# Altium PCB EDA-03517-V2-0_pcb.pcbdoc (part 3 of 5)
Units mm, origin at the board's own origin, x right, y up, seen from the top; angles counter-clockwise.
Board outline 220 x 264 mm, 8 copper layers (Top Layer, L2, L3, L4, L5, L6, L7, Bottom Layer), stack 2.18 mm thick; 439 components, 290 nets, 1011 pads, 273 vias.
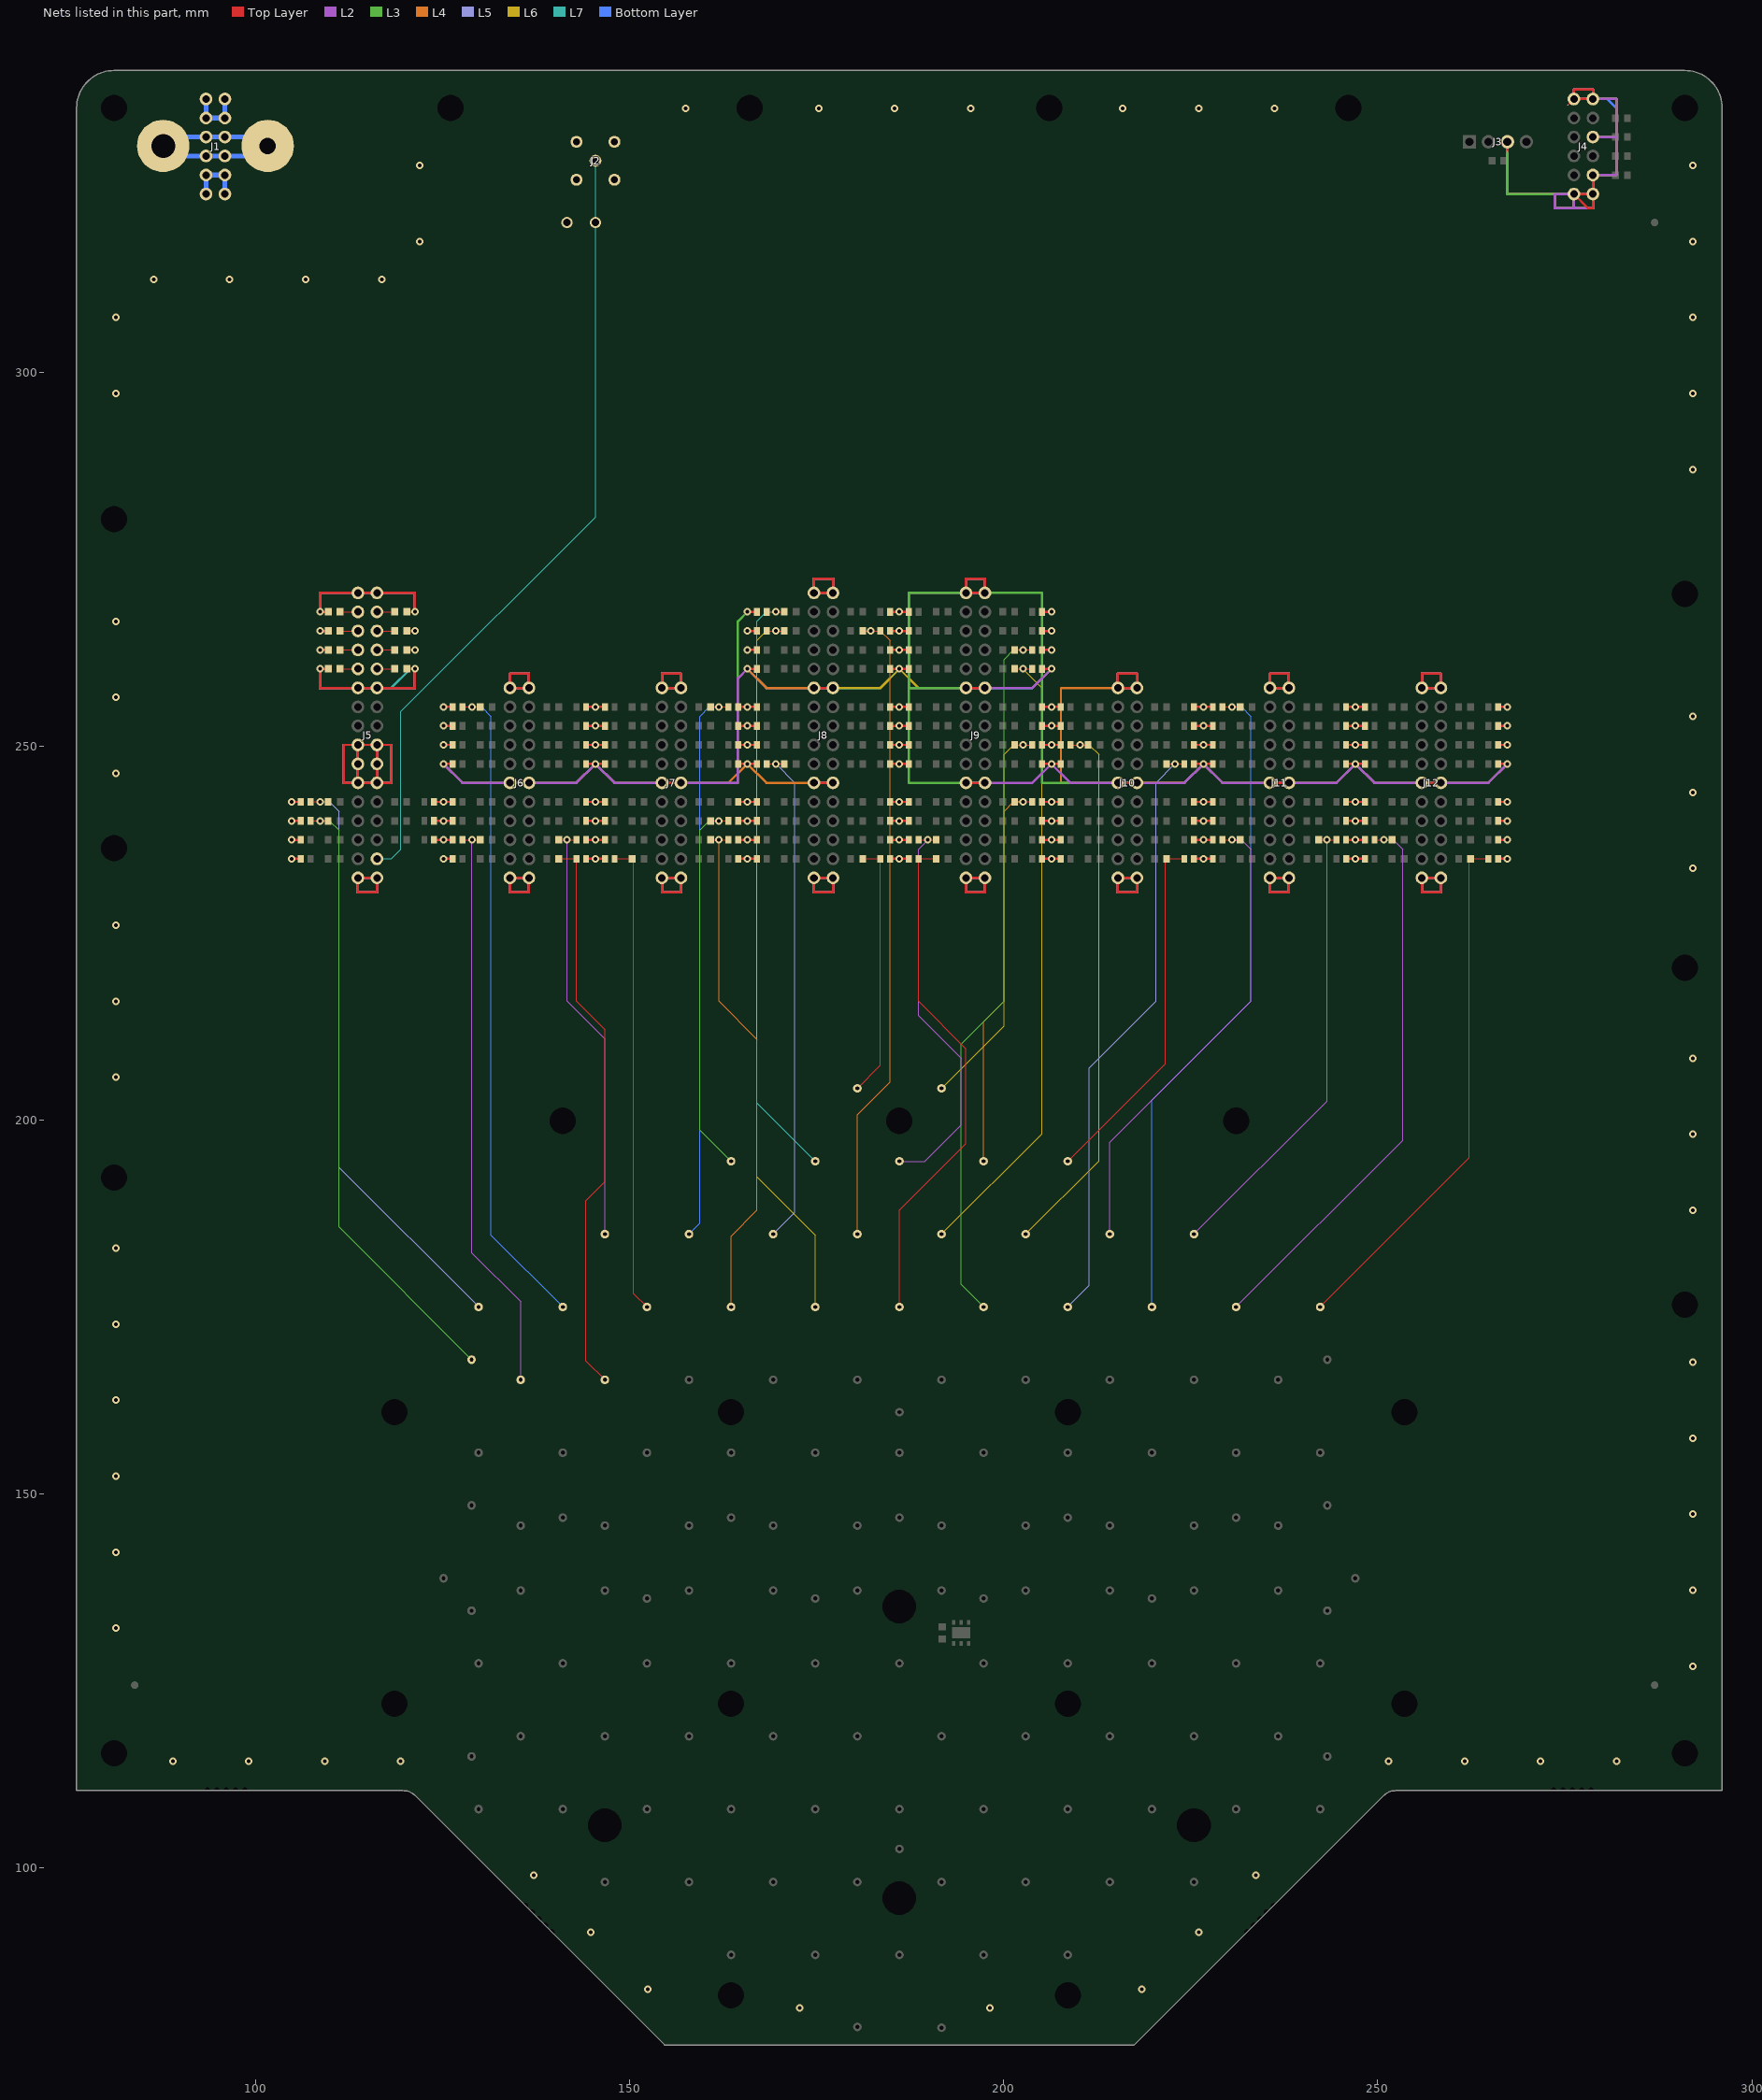
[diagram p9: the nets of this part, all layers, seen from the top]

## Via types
v1: diameter 1, hole 0.5, Top Layer to Bottom Layer, tented both sides, 273 vias

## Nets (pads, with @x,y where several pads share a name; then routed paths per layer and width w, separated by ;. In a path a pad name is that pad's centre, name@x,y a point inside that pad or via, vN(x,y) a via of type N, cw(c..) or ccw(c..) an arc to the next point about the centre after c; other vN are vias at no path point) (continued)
GND: B2.1 C2.2 C3.2 C4.2 C5.2 C6.2 C7.2 C8.2 C9.2 J2.2 J3.3 J4.1 J4.2 J4.3 J4.7 J4.11 J4.12 J5.1 J5.2 J5.11 J5.12 J5.13 J5.14 J5.15 J5.16 J5.21 J5.22 J5.31 J5.32 J6.1 J6.2 J6.11 J6.12 J6.21 J6.22 J7.1 J7.2 J7.11 J7.12 J7.21 J7.22 J8.1 J8.2 J8.11 J8.12 J8.21 J8.22 J8.31 J8.32 J9.1 J9.2 J9.11 J9.12 J9.21 J9.22 J9.31 J9.32 J10.1 J10.2 J10.11 J10.12 J10.21 J10.22 J11.1 J11.2 J11.11 J11.12 J11.21 J11.22 J12.1 J12.2 J12.11 J12.12 J12.21 J12.22 NT1.1 NT2.1 RB1.2 RB2.2 RB3.2 RB4.2 RB5.2 RB6.2 RB7.2 RB8.2 RB9.2 RB10.2 RB11.2 RB12.2 RB13.2 RB14.2 RB15.2 RB16.2 RB17.2 RB18.2 RB19.2 RB20.2 RB21.2 RB22.2 RB23.2 RB24.2 RB25.2 RB26.2 RB27.2 RB28.2 RB29.2 RB30.2 RB31.2 RB32.2 RB33.2 RB34.2 RB35.2 RB36.2 RB37.2 RB38.2 RB39.2 RB40.2 RB41.2 RB42.2 RB43.2 RB44.2 RB45.2 RB46.2 RB47.2 RB48.2 RB49.2 RB50.2 RB51.2 RB52.2 RB53.2 RB54.2 RB55.2 RB56.2 RB57.2 RB58.2 RB59.2 RB60.2 RB61.2 RB62.2 RB63.2 RB64.2 RB65.2 RB66.2 RB67.2 RB68.2 RB69.2 RB70.2 RB71.2 RB72.2 RB73.2 RB74.2 RB75.2 RB76.2 RB77.2 RB78.2 RB79.2 RB80.2 RB81.2 RB82.2 RB83.2 RB84.2 RB85.2 RB86.2 RB87.2 RB88.2 RB89.2 RB90.2 RB91.2 RB92.2 RB93.2 RB94.2 RB95.2 RB96.2 RB97.2 RB98.2 RB99.2 RB100.2 RB101.2 RB102.2 RB103.2 RB104.2 RB105.2 RB106.2 RB107.2 RB108.2 RB109.2 RB110.2 RB111.2 RB112.2 RB113.2 RB114.2 RB115.2 RB116.2 RB117.2 RB118.2 RB119.2 RB120.2 RB121.2 RB122.2 RB123.2 RB124.2 RB125.2 RB126.2 RB127.2 RB128.2 RB129.2 RB130.2 RB131.2 RB132.2 RB133.2 RB134.2 RB135.2 | length 2863.4
  Top Layer w0.152: NT1.1@275.41,335.735 J4.12@276.225,336.55
  Top Layer w0.305: v1(104.775,234.95) RB121.2@106.03,234.95 ; v1(104.775,237.49) RB105.2@106.03,237.49 ; v1(104.775,240.03) RB89.2@106.03,240.03 ; v1(104.775,242.57) RB73.2@106.03,242.57 ; v1(108.585,262.89) C6.2@109.69,262.89 ; v1(108.585,265.43) C4.2@109.69,265.43 ; C8.2@109.69,260.35 v1(108.585,260.35) 108.585,257.81 J5.22@113.665,257.81 J5.21@116.205,257.81 121.285,257.81 v1(121.285,260.35) C9.2@120.18,260.35 ; C2.2@109.69,267.97 v1(108.585,267.97) 108.585,270.51 J5.32@113.665,270.51 J5.31@116.205,270.51 121.285,270.51 v1(121.285,267.97) C3.2@120.18,267.97 ; C7.2@120.18,262.89 v1(121.285,262.89) ; C5.2@120.18,265.43 v1(121.285,265.43) ; RB106.2@123.84,237.49 v1(125.095,237.49) RB112.2@126.35,237.49 ; RB90.2@123.84,240.03 v1(125.095,240.03) RB96.2@126.35,240.03 ; RB74.2@123.84,242.57 v1(125.095,242.57) RB80.2@126.35,242.57 ; v1(125.095,234.95) RB127.2@126.35,234.95 ; v1(125.095,247.65) RB59.2@126.35,247.65 ; v1(125.095,250.19) RB45.2@126.35,250.19 ; v1(125.095,252.73) RB31.2@126.35,252.73 ; v1(125.095,255.27) RB17.2@126.35,255.27 ; J6.12@133.985,245.11 J6.11@136.525,245.11 ; RB122.2@144.16,234.95 v1(145.415,234.95) RB123.2@146.67,234.95 ; RB107.2@144.16,237.49 v1(145.415,237.49) RB108.2@146.67,237.49 ; RB91.2@144.16,240.03 v1(145.415,240.03) RB92.2@146.67,240.03 ; RB75.2@144.16,242.57 v1(145.415,242.57) RB76.2@146.67,242.57 ; RB60.2@144.16,247.65 v1(145.415,247.65) RB61.2@146.67,247.65 ; RB46.2@144.16,250.19 v1(145.415,250.19) RB47.2@146.67,250.19 ; RB32.2@144.16,252.73 v1(145.415,252.73) RB33.2@146.67,252.73 ; RB18.2@144.16,255.27 v1(145.415,255.27) RB19.2@146.67,255.27 ; J7.12@154.305,245.11 J7.11@156.845,245.11 ; RB128.2@164.48,234.95 v1(165.735,234.95) RB124.2@166.99,234.95 ; RB113.2@164.48,237.49 v1(165.735,237.49) RB109.2@166.99,237.49 ; RB97.2@164.48,240.03 v1(165.735,240.03) RB93.2@166.99,240.03 ; RB81.2@164.48,242.57 v1(165.735,242.57) RB77.2@166.99,242.57 ; RB62.2@164.48,247.65 v1(165.735,247.65) RB63.2@166.99,247.65 ; RB48.2@164.48,250.19 v1(165.735,250.19) RB49.2@166.99,250.19 ; RB34.2@164.48,252.73 v1(165.735,252.73) RB35.2@166.99,252.73 ; RB20.2@164.48,255.27 v1(165.735,255.27) RB21.2@166.99,255.27 ; v1(165.735,260.35) RB13.2@166.99,260.35 ; v1(165.735,262.89) RB9.2@166.99,262.89 ; v1(165.735,265.43) RB5.2@166.99,265.43 ; v1(165.735,267.97) RB1.2@166.99,267.97 ; J8.12@174.625,245.11 J8.11@177.165,245.11 ; J8.22@174.625,257.81 J8.21@177.165,257.81 ; RB125.2@184.8,234.95 v1(186.055,234.95) RB129.2@187.31,234.95 ; RB110.2@184.8,237.49 v1(186.055,237.49) RB114.2@187.31,237.49 ; RB94.2@184.8,240.03 v1(186.055,240.03) RB98.2@187.31,240.03 ; RB78.2@184.8,242.57 v1(186.055,242.57) RB82.2@187.31,242.57 ; RB64.2@184.8,247.65 v1(186.055,247.65) RB66.2@187.31,247.65 ; RB50.2@184.8,250.19 v1(186.055,250.19) RB52.2@187.31,250.19 ; RB36.2@184.8,252.73 v1(186.055,252.73) RB38.2@187.31,252.73 ; RB22.2@184.8,255.27 v1(186.055,255.27) RB24.2@187.31,255.27 ; RB14.2@184.8,260.35 v1(186.055,260.35) RB16.2@187.31,260.35 ; RB10.2@184.8,262.89 v1(186.055,262.89) RB12.2@187.31,262.89 ; RB6.2@184.8,265.43 v1(186.055,265.43) RB8.2@187.31,265.43 ; RB2.2@184.8,267.97 v1(186.055,267.97) RB4.2@187.31,267.97 ; J9.12@194.945,245.11 J9.11@197.485,245.11 ; J9.22@194.945,257.81 J9.21@197.485,257.81 ; RB126.2@205.12,234.95 v1(206.375,234.95) RB130.2@207.63,234.95 ; RB111.2@205.12,237.49 v1(206.375,237.49) RB115.2@207.63,237.49 ; RB95.2@205.12,240.03 v1(206.375,240.03) RB99.2@207.63,240.03 ; RB79.2@205.12,242.57 v1(206.375,242.57) RB83.2@207.63,242.57 ; RB65.2@205.12,247.65 v1(206.375,247.65) RB67.2@207.63,247.65 ; RB51.2@205.12,250.19 v1(206.375,250.19) RB53.2@207.63,250.19 ; RB37.2@205.12,252.73 v1(206.375,252.73) RB39.2@207.63,252.73 ; RB23.2@205.12,255.27 v1(206.375,255.27) RB25.2@207.63,255.27 ; RB15.2@205.12,260.35 v1(206.375,260.35) ; RB11.2@205.12,262.89 v1(206.375,262.89) ; RB7.2@205.12,265.43 v1(206.375,265.43) ; RB3.2@205.12,267.97 v1(206.375,267.97) ; J10.12@215.265,245.11 J10.11@217.805,245.11 ; RB131.2@225.44,234.95 v1(226.695,234.95) RB132.2@227.95,234.95 ; RB116.2@225.44,237.49 v1(226.695,237.49) RB117.2@227.95,237.49 ; RB100.2@225.44,240.03 v1(226.695,240.03) RB101.2@227.95,240.03 ; RB84.2@225.44,242.57 v1(226.695,242.57) RB85.2@227.95,242.57 ; RB68.2@225.44,247.65 RB69.2@227.95,247.65 ; RB54.2@225.44,250.19 RB55.2@227.95,250.19 ; RB40.2@225.44,252.73 v1(226.695,252.73) RB41.2@227.95,252.73 ; RB26.2@225.44,255.27 v1(226.695,255.27) RB27.2@227.95,255.27 ; J11.12@235.585,245.11 J11.11@238.125,245.11 ; RB118.2@245.76,237.49 v1(247.015,237.49) RB119.2@248.27,237.49 ; RB102.2@245.76,240.03 v1(247.015,240.03) RB103.2@248.27,240.03 ; RB86.2@245.76,242.57 v1(247.015,242.57) RB87.2@248.27,242.57 ; RB70.2@245.76,247.65 v1(247.015,247.65) RB71.2@248.27,247.65 ; RB56.2@245.76,250.19 v1(247.015,250.19) RB57.2@248.27,250.19 ; RB42.2@245.76,252.73 v1(247.015,252.73) RB43.2@248.27,252.73 ; RB28.2@245.76,255.27 v1(247.015,255.27) RB29.2@248.27,255.27 ; RB133.2@245.775,234.95 v1(247.015,234.95) RB134.2@248.27,234.95 ; J12.12@255.905,245.11 J12.11@258.445,245.11 ; RB135.2@266.08,234.95 v1(267.335,234.95) ; RB120.2@266.08,237.49 v1(267.335,237.49) ; RB104.2@266.08,240.03 v1(267.335,240.03) ; RB88.2@266.08,242.57 v1(267.335,242.57) ; RB72.2@266.08,247.65 v1(267.335,247.65) ; RB58.2@266.08,250.19 v1(267.335,250.19) ; RB44.2@266.08,252.73 v1(267.335,252.73) ; RB30.2@266.08,255.27 v1(267.335,255.27) ; NT2.1@267.335,329.565 J3.3@267.335,330.835 ; J4.3@278.765,326.39 J4.1@278.765,323.85 ; J5.12@113.665,245.11 J5.14@113.665,247.65 J5.16@113.665,250.19 ; J5.12@113.665,245.11 111.76,245.11 111.76,250.19 J5.16@113.665,250.19 ; J5.12@113.665,245.11 J5.11@116.205,245.11 ; J5.16@113.665,250.19 J5.15@116.205,250.19 ; J5.11@116.205,245.11 J5.13@116.205,247.65 J5.15@116.205,250.19 ; J5.11@116.205,245.11 118.11,245.11 118.11,250.19 J5.15@116.205,250.19 ; J4.1@278.765,323.85 278.765,321.945 278.13,321.945 J4.2@276.225,323.85 J4.1@278.765,323.85 ; 113.665,230.505 116.205,230.505 J5.1@116.205,232.41 J5.2@113.665,232.41 113.665,230.505 ; 133.985,230.505 136.525,230.505 J6.1@136.525,232.41 J6.2@133.985,232.41 133.985,230.505 ; J6.22@133.985,257.81 133.985,259.715 136.525,259.715 J6.21@136.525,257.81 J6.22@133.985,257.81 ; 154.305,230.505 156.845,230.505 J7.1@156.845,232.41 J7.2@154.305,232.41 154.305,230.505 ; J7.22@154.305,257.81 154.305,259.715 156.845,259.715 J7.21@156.845,257.81 J7.22@154.305,257.81 ; 174.625,230.505 177.165,230.505 J8.1@177.165,232.41 J8.2@174.625,232.41 174.625,230.505 ; J8.32@174.625,270.51 174.625,272.415 177.165,272.415 J8.31@177.165,270.51 J8.32@174.625,270.51 ; 194.945,230.505 197.485,230.505 J9.1@197.485,232.41 J9.2@194.945,232.41 194.945,230.505 ; J9.32@194.945,270.51 194.945,272.415 197.485,272.415 J9.31@197.485,270.51 J9.32@194.945,270.51 ; 215.265,230.505 217.805,230.505 J10.1@217.805,232.41 J10.2@215.265,232.41 215.265,230.505 ; J10.22@215.265,257.81 215.265,259.715 217.805,259.715 J10.21@217.805,257.81 J10.22@215.265,257.81 ; 235.585,230.505 238.125,230.505 J11.1@238.125,232.41 J11.2@235.585,232.41 235.585,230.505 ; J11.22@235.585,257.81 235.585,259.715 238.125,259.715 J11.21@238.125,257.81 J11.22@235.585,257.81 ; 255.905,230.505 258.445,230.505 J12.1@258.445,232.41 J12.2@255.905,232.41 255.905,230.505 ; J12.22@255.905,257.81 255.905,259.715 258.445,259.715 J12.21@258.445,257.81 J12.22@255.905,257.81 ; J4.12@276.225,336.55 276.225,337.82 278.765,337.82 J4.11@278.765,336.55 J4.12@276.225,336.55
  L2 w0.305: v1(108.585,260.35) 108.585,257.81 J5.22@113.665,257.81 J5.21@116.205,257.81 121.285,257.81 v1(121.285,260.35) ; v1(108.585,267.97) 108.585,270.51 J5.32@113.665,270.51 J5.31@116.205,270.51 121.285,270.51 v1(121.285,267.97) ; v1(125.095,247.65) 127.635,245.11 142.875,245.11 v1(145.415,247.65) 147.955,245.11 J7.12@154.305,245.11 J7.11@156.845,245.11 164.465,245.11 164.465,259.08 v1(165.735,260.35) ; J8.12@174.625,245.11 J8.11@177.165,245.11 ; J8.22@174.625,257.81 J8.21@177.165,257.81 ; J9.12@194.945,245.11 203.835,245.11 v1(206.375,247.65) 208.915,245.11 224.155,245.11 v1(226.695,247.65) 229.235,245.11 J11.12@235.585,245.11 J11.11@238.125,245.11 244.475,245.11 v1(247.015,247.65) 249.555,245.11 J12.12@255.905,245.11 J12.11@258.445,245.11 264.795,245.11 v1(267.335,247.65) ; J9.22@194.945,257.81 203.835,257.81 v1(206.375,260.35) ; J4.7@278.765,331.47 281.94,331.47 ; J5.12@113.665,245.11 111.76,245.11 111.76,250.19 J5.16@113.665,250.19 ; J5.12@113.665,245.11 J5.14@113.665,247.65 J5.16@113.665,250.19 ; J5.12@113.665,245.11 J5.11@116.205,245.11 ; J5.16@113.665,250.19 J5.15@116.205,250.19 ; J5.11@116.205,245.11 118.11,245.11 118.11,250.19 J5.15@116.205,250.19 ; J5.11@116.205,245.11 J5.13@116.205,247.65 J5.15@116.205,250.19 ; 276.225,321.945 273.685,321.945 273.685,323.85 J4.2@276.225,323.85 ; 276.225,321.945 278.765,321.945 J4.1@278.765,323.85 ; 276.225,321.945 J4.2@276.225,323.85 ; J4.2@276.225,323.85 J4.1@278.765,323.85 ; J4.1@278.765,323.85 J4.3@278.765,326.39 281.94,326.39 281.94,331.47 ; J4.11@278.765,336.55 281.94,336.55 281.94,331.47 ; J4.11@278.765,336.55 278.765,337.82 276.225,337.82 J4.12@276.225,336.55 J4.11@278.765,336.55 ; 113.665,230.505 116.205,230.505 J5.1@116.205,232.41 J5.2@113.665,232.41 113.665,230.505 ; 133.985,230.505 136.525,230.505 J6.1@136.525,232.41 J6.2@133.985,232.41 133.985,230.505 ; J6.22@133.985,257.81 133.985,259.715 136.525,259.715 J6.21@136.525,257.81 J6.22@133.985,257.81 ; 154.305,230.505 156.845,230.505 J7.1@156.845,232.41 J7.2@154.305,232.41 154.305,230.505 ; J7.22@154.305,257.81 154.305,259.715 156.845,259.715 J7.21@156.845,257.81 J7.22@154.305,257.81 ; 174.625,230.505 177.165,230.505 J8.1@177.165,232.41 J8.2@174.625,232.41 174.625,230.505 ; J8.32@174.625,270.51 174.625,272.415 177.165,272.415 J8.31@177.165,270.51 J8.32@174.625,270.51 ; 194.945,230.505 197.485,230.505 J9.1@197.485,232.41 J9.2@194.945,232.41 194.945,230.505 ; J9.32@194.945,270.51 194.945,272.415 197.485,272.415 J9.31@197.485,270.51 J9.32@194.945,270.51 ; 215.265,230.505 217.805,230.505 J10.1@217.805,232.41 J10.2@215.265,232.41 215.265,230.505 ; J10.22@215.265,257.81 215.265,259.715 217.805,259.715 J10.21@217.805,257.81 J10.22@215.265,257.81 ; 235.585,230.505 238.125,230.505 J11.1@238.125,232.41 J11.2@235.585,232.41 235.585,230.505 ; J11.22@235.585,257.81 235.585,259.715 238.125,259.715 J11.21@238.125,257.81 J11.22@235.585,257.81 ; 255.905,230.505 258.445,230.505 J12.1@258.445,232.41 J12.2@255.905,232.41 255.905,230.505 ; J12.22@255.905,257.81 255.905,259.715 258.445,259.715 J12.21@258.445,257.81 J12.22@255.905,257.81
  L3 w0.305: v1(108.585,260.35) 108.585,257.81 J5.22@113.665,257.81 J5.21@116.205,257.81 121.285,257.81 v1(121.285,260.35) ; v1(108.585,267.97) 108.585,270.51 J5.32@113.665,270.51 J5.31@116.205,270.51 121.285,270.51 v1(121.285,267.97) ; v1(125.095,247.65) 127.635,245.11 142.875,245.11 v1(145.415,247.65) 147.955,245.11 J7.12@154.305,245.11 J7.11@156.845,245.11 164.465,245.11 164.465,266.7 v1(165.735,267.97) ; J8.12@174.625,245.11 J8.11@177.165,245.11 ; J8.22@174.625,257.81 J8.21@177.165,257.81 ; J9.11@197.485,245.11 187.325,245.11 187.325,257.81 ; J9.21@197.485,257.81 J9.22@194.945,257.81 187.325,257.81 ; J10.11@217.805,245.11 J10.12@215.265,245.11 205.105,245.11 205.105,270.51 J9.31@197.485,270.51 ; v1(226.695,247.65) 229.235,245.11 J11.12@235.585,245.11 J11.11@238.125,245.11 244.475,245.11 v1(247.015,247.65) 249.555,245.11 J12.12@255.905,245.11 J12.11@258.445,245.11 264.795,245.11 v1(267.335,247.65) ; J3.3@267.335,330.835 267.335,323.85 273.685,323.85 ; J4.7@278.765,331.47 281.94,331.47 ; J5.12@113.665,245.11 J5.11@116.205,245.11 ; J5.12@113.665,245.11 J5.14@113.665,247.65 J5.16@113.665,250.19 ; J5.12@113.665,245.11 111.76,245.11 111.76,250.19 J5.16@113.665,250.19 ; J5.16@113.665,250.19 J5.15@116.205,250.19 ; J5.11@116.205,245.11 118.11,245.11 118.11,250.19 J5.15@116.205,250.19 ; J5.11@116.205,245.11 J5.13@116.205,247.65 J5.15@116.205,250.19 ; 187.325,257.81 187.325,270.51 J9.32@194.945,270.51 ; J9.32@194.945,270.51 J9.31@197.485,270.51 ; J9.32@194.945,270.51 194.945,272.415 197.485,272.415 J9.31@197.485,270.51 ; 273.685,323.85 J4.2@276.225,323.85 ; 273.685,323.85 273.685,321.945 276.225,321.945 ; 276.225,321.945 J4.2@276.225,323.85 ; 276.225,321.945 278.765,321.945 J4.1@278.765,323.85 ; J4.2@276.225,323.85 J4.1@278.765,323.85 ; J4.1@278.765,323.85 J4.3@278.765,326.39 281.94,326.39 281.94,331.47 ; J4.11@278.765,336.55 278.765,337.82 276.225,337.82 J4.12@276.225,336.55 J4.11@278.765,336.55 ; J4.11@278.765,336.55 281.94,336.55 281.94,331.47 ; 113.665,230.505 116.205,230.505 J5.1@116.205,232.41 J5.2@113.665,232.41 113.665,230.505 ; 133.985,230.505 136.525,230.505 J6.1@136.525,232.41 J6.2@133.985,232.41 133.985,230.505 ; J6.22@133.985,257.81 J6.21@136.525,257.81 136.525,259.715 133.985,259.715 J6.22@133.985,257.81 ; 154.305,230.505 156.845,230.505 J7.1@156.845,232.41 J7.2@154.305,232.41 154.305,230.505 ; J7.22@154.305,257.81 J7.21@156.845,257.81 156.845,259.715 154.305,259.715 J7.22@154.305,257.81 ; 174.625,230.505 177.165,230.505 J8.1@177.165,232.41 J8.2@174.625,232.41 174.625,230.505 ; J8.32@174.625,270.51 J8.31@177.165,270.51 177.165,272.415 174.625,272.415 J8.32@174.625,270.51 ; 194.945,230.505 197.485,230.505 J9.1@197.485,232.41 J9.2@194.945,232.41 194.945,230.505 ; 215.265,230.505 217.805,230.505 J10.1@217.805,232.41 J10.2@215.265,232.41 215.265,230.505 ; J10.22@215.265,257.81 J10.21@217.805,257.81 217.805,259.715 215.265,259.715 J10.22@215.265,257.81 ; 235.585,230.505 238.125,230.505 J11.1@238.125,232.41 J11.2@235.585,232.41 235.585,230.505 ; J11.22@235.585,257.81 J11.21@238.125,257.81 238.125,259.715 235.585,259.715 J11.22@235.585,257.81 ; 255.905,230.505 258.445,230.505 J12.1@258.445,232.41 J12.2@255.905,232.41 255.905,230.505 ; J12.22@255.905,257.81 J12.21@258.445,257.81 258.445,259.715 255.905,259.715 J12.22@255.905,257.81
  L4 w0.305: v1(108.585,260.35) 108.585,257.81 J5.22@113.665,257.81 J5.21@116.205,257.81 121.285,257.81 v1(121.285,260.35) ; v1(108.585,267.97) 108.585,270.51 J5.32@113.665,270.51 J5.31@116.205,270.51 121.285,270.51 v1(121.285,267.97) ; v1(125.095,247.65) 127.635,245.11 J6.12@133.985,245.11 J6.11@136.525,245.11 142.875,245.11 v1(145.415,247.65) 147.955,245.11 J7.12@154.305,245.11 J7.11@156.845,245.11 163.195,245.11 v1(165.735,247.65) 168.275,245.11 J8.12@174.625,245.11 J8.11@177.165,245.11 ; v1(165.735,260.35) 168.275,257.81 J8.22@174.625,257.81 J8.21@177.165,257.81 ; J9.22@194.945,257.81 J9.21@197.485,257.81 ; v1(267.335,247.65) 264.795,245.11 J12.11@258.445,245.11 J12.12@255.905,245.11 249.555,245.11 v1(247.015,247.65) 244.475,245.11 J11.11@238.125,245.11 J11.12@235.585,245.11 229.235,245.11 v1(226.695,247.65) 224.155,245.11 J10.11@217.805,245.11 J10.12@215.265,245.11 207.645,245.11 207.645,257.81 J10.22@215.265,257.81 ; J3.3@267.335,330.835 267.335,323.85 273.685,323.85 ; J4.7@278.765,331.47 281.94,331.47 ; J5.12@113.665,245.11 111.76,245.11 111.76,250.19 J5.16@113.665,250.19 ; J5.12@113.665,245.11 J5.11@116.205,245.11 ; J5.12@113.665,245.11 J5.14@113.665,247.65 J5.16@113.665,250.19 ; J5.16@113.665,250.19 J5.15@116.205,250.19 ; J5.11@116.205,245.11 118.11,245.11 118.11,250.19 J5.15@116.205,250.19 ; J5.11@116.205,245.11 J5.13@116.205,247.65 J5.15@116.205,250.19 ; J10.22@215.265,257.81 J10.21@217.805,257.81 217.805,259.715 215.265,259.715 J10.22@215.265,257.81 ; 273.685,323.85 J4.2@276.225,323.85 ; 273.685,323.85 273.685,321.945 276.225,321.945 ; 276.225,321.945 J4.2@276.225,323.85 ; 276.225,321.945 278.765,321.945 J4.1@278.765,323.85 ; J4.2@276.225,323.85 J4.1@278.765,323.85 ; J4.1@278.765,323.85 J4.3@278.765,326.39 281.94,326.39 281.94,331.47 ; J4.11@278.765,336.55 281.94,336.55 281.94,331.47 ; J4.11@278.765,336.55 278.765,337.82 276.225,337.82 J4.12@276.225,336.55 J4.11@278.765,336.55 ; 113.665,230.505 116.205,230.505 J5.1@116.205,232.41 J5.2@113.665,232.41 113.665,230.505 ; 133.985,230.505 136.525,230.505 J6.1@136.525,232.41 J6.2@133.985,232.41 133.985,230.505 ; J6.22@133.985,257.81 J6.21@136.525,257.81 136.525,259.715 133.985,259.715 J6.22@133.985,257.81 ; 154.305,230.505 156.845,230.505 J7.1@156.845,232.41 J7.2@154.305,232.41 154.305,230.505 ; J7.22@154.305,257.81 J7.21@156.845,257.81 156.845,259.715 154.305,259.715 J7.22@154.305,257.81 ; 174.625,230.505 177.165,230.505 J8.1@177.165,232.41 J8.2@174.625,232.41 174.625,230.505 ; J8.32@174.625,270.51 J8.31@177.165,270.51 177.165,272.415 174.625,272.415 J8.32@174.625,270.51 ; 194.945,230.505 197.485,230.505 J9.1@197.485,232.41 J9.2@194.945,232.41 194.945,230.505 ; J9.32@194.945,270.51 J9.31@197.485,270.51 197.485,272.415 194.945,272.415 J9.32@194.945,270.51 ; 215.265,230.505 217.805,230.505 J10.1@217.805,232.41 J10.2@215.265,232.41 215.265,230.505 ; 235.585,230.505 238.125,230.505 J11.1@238.125,232.41 J11.2@235.585,232.41 235.585,230.505 ; J11.22@235.585,257.81 J11.21@238.125,257.81 238.125,259.715 235.585,259.715 J11.22@235.585,257.81 ; 255.905,230.505 258.445,230.505 J12.1@258.445,232.41 J12.2@255.905,232.41 255.905,230.505 ; J12.22@255.905,257.81 J12.21@258.445,257.81 258.445,259.715 255.905,259.715 J12.22@255.905,257.81
  L5 w0.305: v1(108.585,260.35) 108.585,257.81 J5.22@113.665,257.81 J5.21@116.205,257.81 121.285,257.81 v1(121.285,260.35) ; v1(108.585,267.97) 108.585,270.51 J5.32@113.665,270.51 J5.31@116.205,270.51 121.285,270.51 v1(121.285,267.97) ; J6.12@133.985,245.11 J6.11@136.525,245.11 ; J7.12@154.305,245.11 J7.11@156.845,245.11 ; v1(165.735,260.35) 168.275,257.81 J8.22@174.625,257.81 J8.21@177.165,257.81 ; J8.12@174.625,245.11 J8.11@177.165,245.11 ; J9.21@197.485,257.81 J9.22@194.945,257.81 187.325,257.81 187.325,270.51 J9.32@194.945,270.51 ; J10.12@215.265,245.11 J10.11@217.805,245.11 ; J11.12@235.585,245.11 J11.11@238.125,245.11 ; J12.12@255.905,245.11 J12.11@258.445,245.11 ; J3.3@267.335,330.835 267.335,323.85 273.685,323.85 ; J4.7@278.765,331.47 281.94,331.47 ; J5.12@113.665,245.11 J5.14@113.665,247.65 J5.16@113.665,250.19 ; J5.12@113.665,245.11 111.76,245.11 111.76,250.19 J5.16@113.665,250.19 ; J5.12@113.665,245.11 J5.11@116.205,245.11 ; J5.16@113.665,250.19 J5.15@116.205,250.19 ; J5.11@116.205,245.11 J5.13@116.205,247.65 J5.15@116.205,250.19 ; J5.11@116.205,245.11 118.11,245.11 118.11,250.19 J5.15@116.205,250.19 ; J9.32@194.945,270.51 194.945,272.415 197.485,272.415 J9.31@197.485,270.51 J9.32@194.945,270.51 ; 273.685,323.85 J4.2@276.225,323.85 ; 273.685,323.85 273.685,321.945 276.225,321.945 ; 276.225,321.945 J4.2@276.225,323.85 ; 276.225,321.945 278.765,321.945 J4.1@278.765,323.85 ; J4.2@276.225,323.85 J4.1@278.765,323.85 ; J4.1@278.765,323.85 J4.3@278.765,326.39 281.94,326.39 281.94,331.47 ; J4.11@278.765,336.55 278.765,337.82 276.225,337.82 J4.12@276.225,336.55 J4.11@278.765,336.55 ; J4.11@278.765,336.55 281.94,336.55 281.94,331.47 ; 113.665,230.505 J5.2@113.665,232.41 J5.1@116.205,232.41 116.205,230.505 113.665,230.505 ; 133.985,230.505 J6.2@133.985,232.41 J6.1@136.525,232.41 136.525,230.505 133.985,230.505 ; J6.22@133.985,257.81 133.985,259.715 136.525,259.715 J6.21@136.525,257.81 J6.22@133.985,257.81 ; 154.305,230.505 J7.2@154.305,232.41 J7.1@156.845,232.41 156.845,230.505 154.305,230.505 ; J7.22@154.305,257.81 154.305,259.715 156.845,259.715 J7.21@156.845,257.81 J7.22@154.305,257.81 ; 174.625,230.505 J8.2@174.625,232.41 J8.1@177.165,232.41 177.165,230.505 174.625,230.505 ; J8.32@174.625,270.51 174.625,272.415 177.165,272.415 J8.31@177.165,270.51 J8.32@174.625,270.51 ; 194.945,230.505 J9.2@194.945,232.41 J9.1@197.485,232.41 197.485,230.505 194.945,230.505 ; 215.265,230.505 J10.2@215.265,232.41 J10.1@217.805,232.41 217.805,230.505 215.265,230.505 ; J10.22@215.265,257.81 215.265,259.715 217.805,259.715 J10.21@217.805,257.81 J10.22@215.265,257.81 ; 235.585,230.505 J11.2@235.585,232.41 J11.1@238.125,232.41 238.125,230.505 235.585,230.505 ; J11.22@235.585,257.81 235.585,259.715 238.125,259.715 J11.21@238.125,257.81 J11.22@235.585,257.81 ; 255.905,230.505 J12.2@255.905,232.41 J12.1@258.445,232.41 258.445,230.505 255.905,230.505 ; J12.22@255.905,257.81 255.905,259.715 258.445,259.715 J12.21@258.445,257.81 J12.22@255.905,257.81
  L6 w0.305: v1(108.585,260.35) 108.585,257.81 J5.22@113.665,257.81 J5.21@116.205,257.81 121.285,257.81 v1(121.285,260.35) ; v1(108.585,267.97) 108.585,270.51 J5.32@113.665,270.51 J5.31@116.205,270.51 121.285,270.51 v1(121.285,267.97) ; J6.12@133.985,245.11 J6.11@136.525,245.11 ; J7.12@154.305,245.11 J7.11@156.845,245.11 ; J8.12@174.625,245.11 J8.11@177.165,245.11 ; J8.22@174.625,257.81 J8.21@177.165,257.81 183.515,257.81 v1(186.055,260.35) 188.595,257.81 J9.22@194.945,257.81 J9.21@197.485,257.81 ; J10.12@215.265,245.11 J10.11@217.805,245.11 ; J11.12@235.585,245.11 J11.11@238.125,245.11 ; J12.12@255.905,245.11 J12.11@258.445,245.11 ; J3.3@267.335,330.835 267.335,323.85 273.685,323.85 ; J4.7@278.765,331.47 281.94,331.47 ; J5.12@113.665,245.11 J5.14@113.665,247.65 J5.16@113.665,250.19 ; J5.12@113.665,245.11 111.76,245.11 111.76,250.19 J5.16@113.665,250.19 ; J5.12@113.665,245.11 J5.11@116.205,245.11 ; J5.16@113.665,250.19 J5.15@116.205,250.19 ; J5.11@116.205,245.11 J5.13@116.205,247.65 J5.15@116.205,250.19 ; J5.11@116.205,245.11 118.11,245.11 118.11,250.19 J5.15@116.205,250.19 ; 273.685,323.85 J4.2@276.225,323.85 ; 273.685,323.85 273.685,321.945 276.225,321.945 ; 276.225,321.945 J4.2@276.225,323.85 ; 276.225,321.945 278.765,321.945 J4.1@278.765,323.85 ; J4.2@276.225,323.85 J4.1@278.765,323.85 ; J4.1@278.765,323.85 J4.3@278.765,326.39 281.94,326.39 281.94,331.47 ; J4.11@278.765,336.55 278.765,337.82 276.225,337.82 J4.12@276.225,336.55 J4.11@278.765,336.55 ; J4.11@278.765,336.55 281.94,336.55 281.94,331.47 ; 113.665,230.505 J5.2@113.665,232.41 J5.1@116.205,232.41 116.205,230.505 113.665,230.505 ; 133.985,230.505 J6.2@133.985,232.41 J6.1@136.525,232.41 136.525,230.505 133.985,230.505 ; J6.22@133.985,257.81 133.985,259.715 136.525,259.715 J6.21@136.525,257.81 J6.22@133.985,257.81 ; 154.305,230.505 J7.2@154.305,232.41 J7.1@156.845,232.41 156.845,230.505 154.305,230.505 ; J7.22@154.305,257.81 154.305,259.715 156.845,259.715 J7.21@156.845,257.81 J7.22@154.305,257.81 ; 174.625,230.505 J8.2@174.625,232.41 J8.1@177.165,232.41 177.165,230.505 174.625,230.505 ; J8.32@174.625,270.51 174.625,272.415 177.165,272.415 J8.31@177.165,270.51 J8.32@174.625,270.51 ; 194.945,230.505 J9.2@194.945,232.41 J9.1@197.485,232.41 197.485,230.505 194.945,230.505 ; J9.32@194.945,270.51 194.945,272.415 197.485,272.415 J9.31@197.485,270.51 J9.32@194.945,270.51 ; 215.265,230.505 J10.2@215.265,232.41 J10.1@217.805,232.41 217.805,230.505 215.265,230.505 ; J10.22@215.265,257.81 215.265,259.715 217.805,259.715 J10.21@217.805,257.81 J10.22@215.265,257.81 ; 235.585,230.505 J11.2@235.585,232.41 J11.1@238.125,232.41 238.125,230.505 235.585,230.505 ; J11.22@235.585,257.81 235.585,259.715 238.125,259.715 J11.21@238.125,257.81 J11.22@235.585,257.81 ; 255.905,230.505 J12.2@255.905,232.41 J12.1@258.445,232.41 258.445,230.505 255.905,230.505 ; J12.22@255.905,257.81 255.905,259.715 258.445,259.715 J12.21@258.445,257.81 J12.22@255.905,257.81
  L7 w0.305: v1(108.585,260.35) 108.585,257.81 J5.22@113.665,257.81 J5.21@116.205,257.81 118.11,257.81 120.65,260.35 v1(121.285,260.35) ; v1(108.585,267.97) 108.585,270.51 J5.32@113.665,270.51 J5.31@116.205,270.51 121.285,270.51 v1(121.285,267.97) ; J6.12@133.985,245.11 J6.11@136.525,245.11 ; J7.12@154.305,245.11 J7.11@156.845,245.11 ; J8.12@174.625,245.11 J8.11@177.165,245.11 ; J8.22@174.625,257.81 J8.21@177.165,257.81 183.515,257.81 v1(186.055,260.35) ; J9.22@194.945,257.81 J9.21@197.485,257.81 203.835,257.81 v1(206.375,260.35) ; J10.12@215.265,245.11 J10.11@217.805,245.11 ; J11.12@235.585,245.11 J11.11@238.125,245.11 ; J12.12@255.905,245.11 J12.11@258.445,245.11 ; J3.3@267.335,330.835 267.335,323.85 273.685,323.85 ; J4.7@278.765,331.47 281.94,331.47 ; J5.12@113.665,245.11 J5.14@113.665,247.65 J5.16@113.665,250.19 ; J5.12@113.665,245.11 111.76,245.11 111.76,250.19 J5.16@113.665,250.19 ; J5.12@113.665,245.11 J5.11@116.205,245.11 J5.13@116.205,247.65 J5.15@116.205,250.19 J5.16@113.665,250.19 ; 273.685,323.85 J4.2@276.225,323.85 ; 273.685,323.85 273.685,321.945 276.225,321.945 ; 276.225,321.945 J4.2@276.225,323.85 ; 276.225,321.945 278.765,321.945 J4.1@278.765,323.85 ; J4.2@276.225,323.85 J4.1@278.765,323.85 ; J4.1@278.765,323.85 J4.3@278.765,326.39 281.94,326.39 281.94,331.47 ; J4.11@278.765,336.55 281.94,336.55 281.94,331.47 ; J4.11@278.765,336.55 278.765,337.82 276.225,337.82 J4.12@276.225,336.55 J4.11@278.765,336.55 ; 113.665,230.505 J5.2@113.665,232.41 J5.1@116.205,232.41 116.205,230.505 113.665,230.505 ; 133.985,230.505 J6.2@133.985,232.41 J6.1@136.525,232.41 136.525,230.505 133.985,230.505 ; J6.22@133.985,257.81 133.985,259.715 136.525,259.715 J6.21@136.525,257.81 J6.22@133.985,257.81 ; 154.305,230.505 J7.2@154.305,232.41 J7.1@156.845,232.41 156.845,230.505 154.305,230.505 ; J7.22@154.305,257.81 154.305,259.715 156.845,259.715 J7.21@156.845,257.81 J7.22@154.305,257.81 ; 174.625,230.505 J8.2@174.625,232.41 J8.1@177.165,232.41 177.165,230.505 174.625,230.505 ; J8.32@174.625,270.51 174.625,272.415 177.165,272.415 J8.31@177.165,270.51 J8.32@174.625,270.51 ; 194.945,230.505 J9.2@194.945,232.41 J9.1@197.485,232.41 197.485,230.505 194.945,230.505 ; J9.32@194.945,270.51 194.945,272.415 197.485,272.415 J9.31@197.485,270.51 J9.32@194.945,270.51 ; 215.265,230.505 J10.2@215.265,232.41 J10.1@217.805,232.41 217.805,230.505 215.265,230.505 ; J10.22@215.265,257.81 215.265,259.715 217.805,259.715 J10.21@217.805,257.81 J10.22@215.265,257.81 ; 235.585,230.505 J11.2@235.585,232.41 J11.1@238.125,232.41 238.125,230.505 235.585,230.505 ; J11.22@235.585,257.81 235.585,259.715 238.125,259.715 J11.21@238.125,257.81 J11.22@235.585,257.81 ; 255.905,230.505 J12.2@255.905,232.41 J12.1@258.445,232.41 258.445,230.505 255.905,230.505 ; J12.22@255.905,257.81 255.905,259.715 258.445,259.715 J12.21@258.445,257.81 J12.22@255.905,257.81
  Bottom Layer w0.305: v1(108.585,260.35) 108.585,257.81 J5.22@113.665,257.81 J5.21@116.205,257.81 121.285,257.81 v1(121.285,260.35) ; v1(108.585,267.97) 108.585,270.51 J5.32@113.665,270.51 J5.31@116.205,270.51 121.285,270.51 v1(121.285,267.97) ; J6.2@133.985,232.41 J6.1@136.525,232.41 ; J6.12@133.985,245.11 J6.11@136.525,245.11 ; J7.2@154.305,232.41 J7.1@156.845,232.41 ; J7.12@154.305,245.11 J7.11@156.845,245.11 ; J8.2@174.625,232.41 J8.1@177.165,232.41 ; J8.12@174.625,245.11 J8.11@177.165,245.11 ; J8.22@174.625,257.81 J8.21@177.165,257.81 ; J9.2@194.945,232.41 J9.1@197.485,232.41 ; J9.22@194.945,257.81 J9.21@197.485,257.81 ; J10.2@215.265,232.41 J10.1@217.805,232.41 ; J10.12@215.265,245.11 J10.11@217.805,245.11 ; J11.2@235.585,232.41 J11.1@238.125,232.41 ; J11.12@235.585,245.11 J11.11@238.125,245.11 ; J12.2@255.905,232.41 J12.1@258.445,232.41 ; J12.12@255.905,245.11 J12.11@258.445,245.11 ; J3.3@267.335,330.835 267.335,323.85 273.685,323.85 ; J4.12@276.225,336.55 J4.11@278.765,336.55 280.67,336.55 281.94,335.28 281.94,331.47 ; J4.7@278.765,331.47 281.94,331.47 ; J5.12@113.665,245.11 J5.14@113.665,247.65 J5.16@113.665,250.19 ; J5.12@113.665,245.11 111.76,245.11 111.76,250.19 J5.16@113.665,250.19 ; J5.12@113.665,245.11 J5.11@116.205,245.11 ; J5.16@113.665,250.19 J5.15@116.205,250.19 ; J5.11@116.205,245.11 J5.13@116.205,247.65 J5.15@116.205,250.19 ; J5.11@116.205,245.11 118.11,245.11 118.11,250.19 J5.15@116.205,250.19 ; 273.685,323.85 J4.2@276.225,323.85 ; 273.685,323.85 273.685,321.945 276.225,321.945 ; 276.225,321.945 J4.2@276.225,323.85 ; 276.225,321.945 278.765,321.945 J4.1@278.765,323.85 ; J4.2@276.225,323.85 J4.1@278.765,323.85 ; J4.1@278.765,323.85 J4.3@278.765,326.39 281.94,326.39 281.94,331.47 ; 113.665,230.505 J5.2@113.665,232.41 J5.1@116.205,232.41 116.205,230.505 113.665,230.505 ; J6.22@133.985,257.81 133.985,259.715 136.525,259.715 J6.21@136.525,257.81 J6.22@133.985,257.81 ; J7.22@154.305,257.81 154.305,259.715 156.845,259.715 J7.21@156.845,257.81 J7.22@154.305,257.81 ; J8.32@174.625,270.51 174.625,272.415 177.165,272.415 J8.31@177.165,270.51 J8.32@174.625,270.51 ; J9.32@194.945,270.51 194.945,272.415 197.485,272.415 J9.31@197.485,270.51 J9.32@194.945,270.51 ; J10.22@215.265,257.81 215.265,259.715 217.805,259.715 J10.21@217.805,257.81 J10.22@215.265,257.81 ; J11.22@235.585,257.81 235.585,259.715 238.125,259.715 J11.21@238.125,257.81 J11.22@235.585,257.81 ; J12.22@255.905,257.81 255.905,259.715 258.445,259.715 J12.21@258.445,257.81 J12.22@255.905,257.81
  other v1: 172.72,81.28 198.12,81.28 152.4,83.82 218.44,83.82 144.78,91.44 226.06,91.44 137.16,99.06 233.68,99.06 88.9,114.3 99.06,114.3 109.22,114.3 119.38,114.3 251.46,114.3 261.62,114.3 271.78,114.3 281.94,114.3 292.1,127 81.28,132.08 292.1,137.16 81.28,142.24 292.1,147.32 81.28,152.4 292.1,157.48 81.28,162.56 292.1,167.64 81.28,172.72 81.28,182.88 292.1,187.96 292.1,198.12 81.28,205.74 292.1,208.28 81.28,215.9 81.28,226.06 292.1,233.68 292.1,243.84 81.28,246.38 226.695,250.19 292.1,254 81.28,256.54 81.28,266.7 292.1,287.02 81.28,297.18 292.1,297.18 81.28,307.34 292.1,307.34 86.36,312.42 96.52,312.42 106.68,312.42 116.84,312.42 121.92,317.5 292.1,317.5 121.92,327.66 292.1,327.66 157.48,335.28 175.26,335.28 185.42,335.28 195.58,335.28 215.9,335.28 226.06,335.28 236.22,335.28
HV: J1.5 J1.6 J1.7 J1.8 pad.P28 pad.P29 | length 30
  Bottom Layer w0.635: pad.P29@87.63,330.282 88.982,328.93 J1.6@93.345,328.93 J1.5@95.885,328.93 100.248,328.93 pad.P28@101.6,330.282 100.412,331.47 J1.7@95.885,331.47 J1.8@93.345,331.47 88.818,331.47 pad.P29@87.63,330.282
HVSH1: J1.9 J1.10 J1.11 J1.12 | length 7.6
  Bottom Layer w0.635: J1.12@93.345,336.55 J1.10@93.345,334.01 J1.9@95.885,334.01 J1.11@95.885,336.55
HVSH2: J1.1 J1.2 J1.3 J1.4 | length 7.6
  Bottom Layer w0.635: J1.2@93.345,323.85 J1.4@93.345,326.39 J1.3@95.885,326.39 J1.1@95.885,323.85
NetB1_1: B1.1 J2.1 J5.3 | length 106.6
  L7 w0.152: J5.3@116.205,234.95 118.11,234.95 119.38,236.22 119.38,254.635 145.415,280.67 B1.1@145.415,320.04 J2.1@145.415,328.295
NetC2_1: C2.1 J5.30 | length 2.4
  Top Layer w0.152: C2.1@111.29,267.97 J5.30@113.665,267.97
NetC3_1: C3.1 J5.29 | length 2.4
  Top Layer w0.152: J5.29@116.205,267.97 C3.1@118.58,267.97
NetC4_1: C4.1 J5.28 | length 2.4
  Top Layer w0.152: C4.1@111.29,265.43 J5.28@113.665,265.43
NetC5_1: C5.1 J5.27 | length 2.4
  Top Layer w0.152: J5.27@116.205,265.43 C5.1@118.58,265.43
NetC6_1: C6.1 J5.26 | length 2.4
  Top Layer w0.152: C6.1@111.29,262.89 J5.26@113.665,262.89
NetC7_1: C7.1 J5.25 | length 2.4
  Top Layer w0.152: J5.25@116.205,262.89 C7.1@118.58,262.89
NetC8_1: C8.1 J5.24 | length 2.4
  Top Layer w0.152: C8.1@111.29,260.35 J5.24@113.665,260.35
NetC9_1: C9.1 J5.23 | length 2.4
  Top Layer w0.152: J5.23@116.205,260.35 C9.1@118.58,260.35
NetPP1_1: PP1.1 RB125.1 RS125.1 | length 34.3
  Top Layer w0.152: PP1.1@180.429,204.261 183.515,207.347 183.515,234.935 RB125.1@183.5,234.95 RS125.1@181.14,234.95
NetPP2_1: PP2.1 RB51.1 RS51.1 | length 53.5
  Top Layer w0.152: RS51.1@201.46,250.19 RB51.1@203.82,250.19
  L6 w0.152: PP2.1@191.681,204.261 200.025,212.605 200.025,248.92 201.295,250.19 v1(202.565,250.19)
NetPP3_1: PP3.1 RB97.1 RS97.1 | length 51.4
  Top Layer w0.152: RS97.1@160.82,240.03 RB97.1@163.18,240.03
  L3 w0.152: v1(161.925,240.03) 160.655,240.03 159.385,238.76 159.385,198.682 PP3.1@163.551,194.516
NetPP4_1: PP4.1 RB1.1 RS1.1 | length 80.8
  Top Layer w0.152: RB1.1@168.29,267.97 v1(169.545,267.97) RS1.1@170.65,267.97
  L7 w0.152: v1(169.545,267.97) 168.275,267.97 167.005,266.7 167.005,202.314 PP4.1@174.803,194.516
NetPP5_1: PP5.1 RB114.1 RS114.1 | length 53.6
  Top Layer w0.152: RB114.1@188.61,237.49 v1(189.865,237.49) RS114.1@190.97,237.49
  L2 w0.152: PP5.1@186.055,194.516 189.436,194.516 194.31,199.39 194.31,208.28 188.595,213.995 188.595,236.22 v1(189.865,237.49)
NetPP6_1: PP6.1 RB79.1 RS79.1 | length 53.3
  Top Layer w0.152: RS79.1@201.46,242.57 v1(202.565,242.57) RB79.1@203.82,242.57
  L4 w0.152: PP6.1@197.307,194.516 197.307,213.182 200.025,215.9 200.025,241.3 201.295,242.57 v1(202.565,242.57)
NetPP7_1: PP7.1 RB131.1 RS131.1 | length 48.3
  Top Layer w0.152: PP7.1@208.559,194.516 221.615,207.572 221.615,234.785 RS131.1@221.78,234.95 RB131.1@224.14,234.95
NetPP8_1: PP8.1 RB107.1 RS107.1 | length 57.2
  Top Layer w0.152: RS107.1@140.5,237.49 RB107.1@142.86,237.49
  L2 w0.152: v1(141.605,237.49) 141.605,215.9 146.673,210.832 PP8.1@146.673,184.772
NetPP9_1: PP9.1 RB20.1 RS20.1 | length 75.3
  Top Layer w0.152: RS20.1@160.82,255.27 RB20.1@163.18,255.27
  Bottom Layer w0.152: PP9.1@157.925,184.772 159.385,186.232 159.385,254 160.655,255.27 v1(161.925,255.27)
NetPP10_1: PP10.1 RB63.1 RS63.1 | length 67.5
  Top Layer w0.152: RB63.1@168.29,247.65 RS63.1@170.65,247.65
  L5 w0.152: PP10.1@169.177,184.772 172.085,187.68 172.085,245.11 v1(169.545,247.65)
NetPP11_1: PP11.1 RB6.1 RS6.1 | length 86.6
  Top Layer w0.152: RS6.1@181.14,265.43 v1(182.245,265.43) RB6.1@183.5,265.43
  L4 w0.152: PP11.1@180.429,184.772 180.429,200.749 184.785,205.105 184.785,264.16 183.515,265.43 v1(182.245,265.43)
NetPP12_1: PP12.1 RB15.1 RS16.1 | length 84.6
  Top Layer w0.152: RS16.1@201.46,260.35 v1(202.565,260.35) RB15.1@203.82,260.35
  L6 w0.152: PP12.1@191.681,184.772 205.105,198.196 205.105,257.81 v1(202.565,260.35)
NetPP13_1: PP13.1 RB53.1 RS53.1 | length 73.6
  Top Layer w0.152: RB53.1@208.93,250.19 v1(210.185,250.19) RS53.1@211.29,250.19
  L6 w0.152: PP13.1@202.933,184.772 212.725,194.564 212.725,248.92 211.455,250.19 v1(210.185,250.19)
NetPP14_1: PP14.1 RB117.1 RS117.1 | length 64.7
  Top Layer w0.152: RB117.1@229.25,237.49 v1(230.505,237.49) RS117.1@231.61,237.49
  L2 w0.152: PP14.1@214.185,184.772 214.185,197.04 233.045,215.9 233.045,236.22 231.775,237.49 v1(230.505,237.49)
NetPP15_1: PP15.1 RB118.1 RS118.1 | length 62.4
  Top Layer w0.152: RS118.1@242.1,237.49 v1(243.205,237.49) RB118.1@244.46,237.49
  L2 w0.152: PP15.1@225.437,184.772 243.205,202.54 v1(243.205,237.49)
NetPP16_1: PP16.1 RB73.1 RS73.1 | length 79.4
  Top Layer w0.152: RB73.1@107.33,242.57 v1(108.585,242.57) RS73.1@109.69,242.57
  L5 w0.152: v1(108.585,242.57) 109.855,242.57 111.125,241.3 111.125,193.697 PP16.1@129.795,175.027
NetPP17_1: PP17.1 RB17.1 RS17.1 | length 88.4
  Top Layer w0.152: RB17.1@127.65,255.27 v1(128.905,255.27) RS17.1@130.01,255.27
  Bottom Layer w0.152: v1(128.905,255.27) 130.175,255.27 131.445,254 131.445,184.629 PP17.1@141.047,175.027
NetPP18_1: PP18.1 RB123.1 RS123.1 | length 63.1
  Top Layer w0.152: RB123.1@147.97,234.95 RS123.1@150.33,234.95 150.495,234.785 150.495,176.831 PP18.1@152.299,175.027
NetPP19_1: PP19.1 RB113.1 RS113.1 | length 68.4
  Top Layer w0.152: RS113.1@160.82,237.49 RB113.1@163.18,237.49
  L4 w0.152: v1(161.925,237.49) 161.925,215.9 167.005,210.82 167.005,187.96 163.551,184.506 PP19.1@163.551,175.027
NetPP20_1: PP20.1 RB5.1 RS5.1 | length 97.8
  Top Layer w0.152: RB5.1@168.29,265.43 v1(169.545,265.43) RS5.1@170.65,265.43
  L6 w0.152: v1(169.545,265.43) 168.275,265.43 167.005,264.16 167.005,192.405 174.803,184.607 PP20.1@174.803,175.027
NetPP21_1: PP21.1 RB129.1 RS129.1 | length 68.6
  Top Layer w0.152: PP21.1@186.055,175.027 186.055,187.96 194.945,196.85 194.945,209.55 188.595,215.9 188.595,234.935 RB129.1@188.61,234.95 RS129.1@190.97,234.95
NetPP22_1: PP22.1 RB11.1 RS12.1 | length 95.6
  Top Layer w0.152: RS12.1@201.46,262.89 v1(202.565,262.89) RB11.1@203.82,262.89
  L3 w0.152: PP22.1@197.307,175.027 194.31,178.024 194.31,210.185 200.025,215.9 200.025,261.62 201.295,262.89 v1(202.565,262.89)
NetPP23_1: PP23.1 RB68.1 RS68.1 | length 80.9
  Top Layer w0.152: RS68.1@221.78,247.65 v1(222.885,247.65) RB68.1@224.14,247.65
  L5 w0.152: PP23.1@208.559,175.027 211.455,177.923 211.455,207.01 220.345,215.9 220.345,245.11 v1(222.885,247.65)
NetPP24_1: PP24.1 RB27.1 RS27.1 | length 89.9
  Top Layer w0.152: RB27.1@229.25,255.27 v1(230.505,255.27) RS27.1@231.61,255.27
  Bottom Layer w0.152: PP24.1@219.811,175.027 219.811,202.666 233.045,215.9 233.045,254 231.775,255.27 v1(230.505,255.27)
NetPP25_1: PP25.1 RB119.1 RS119.1 | length 75.9
  Top Layer w0.152: RB119.1@249.57,237.49 v1(250.825,237.49) RS119.1@251.93,237.49
  L2 w0.152: PP25.1@231.063,175.027 253.365,197.329 253.365,236.22 252.095,237.49 v1(250.825,237.49)
NetPP26_1: PP26.1 RB135.1 RS135.1 | length 70.6
  Top Layer w0.152: PP26.1@242.315,175.027 262.255,194.967 262.255,234.785 RS135.1@262.42,234.95 RB135.1@264.78,234.95
NetPP27_1: PP27.1 RB89.1 RS89.1 | length 83.5
  Top Layer w0.152: RB89.1@107.33,240.03 v1(108.585,240.03) RS89.1@109.69,240.03
  L3 w0.152: v1(108.585,240.03) 109.855,240.03 111.125,238.76 111.125,185.713 PP27.1@128.852,167.986
NetPP28_1: PP28.1 RB112.1 RS112.1 | length 77.3
  Top Layer w0.152: RB112.1@127.65,237.49 v1(128.905,237.49) RS112.1@130.01,237.49
  L2 w0.152: v1(128.905,237.49) 128.905,182.245 135.421,175.729 PP28.1@135.421,165.283
NetPP29_1: PP29.1 RB122.1 RS122.1 | length 75.7
  Top Layer w0.152: RS122.1@140.5,234.95 RB122.1@142.86,234.95 142.875,234.935 142.875,215.9 146.685,212.09 146.685,191.77 144.145,189.23 144.145,167.811 PP29.1@146.673,165.283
